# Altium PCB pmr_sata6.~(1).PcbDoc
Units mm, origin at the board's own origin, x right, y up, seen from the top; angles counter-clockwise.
Board outline 160 x 99.92 mm, 2 copper layers (Top Layer, Bottom Layer); 10 components, 40 nets, 165 pads, 0 vias.
Unrouted connection lines stored in the file: 105.
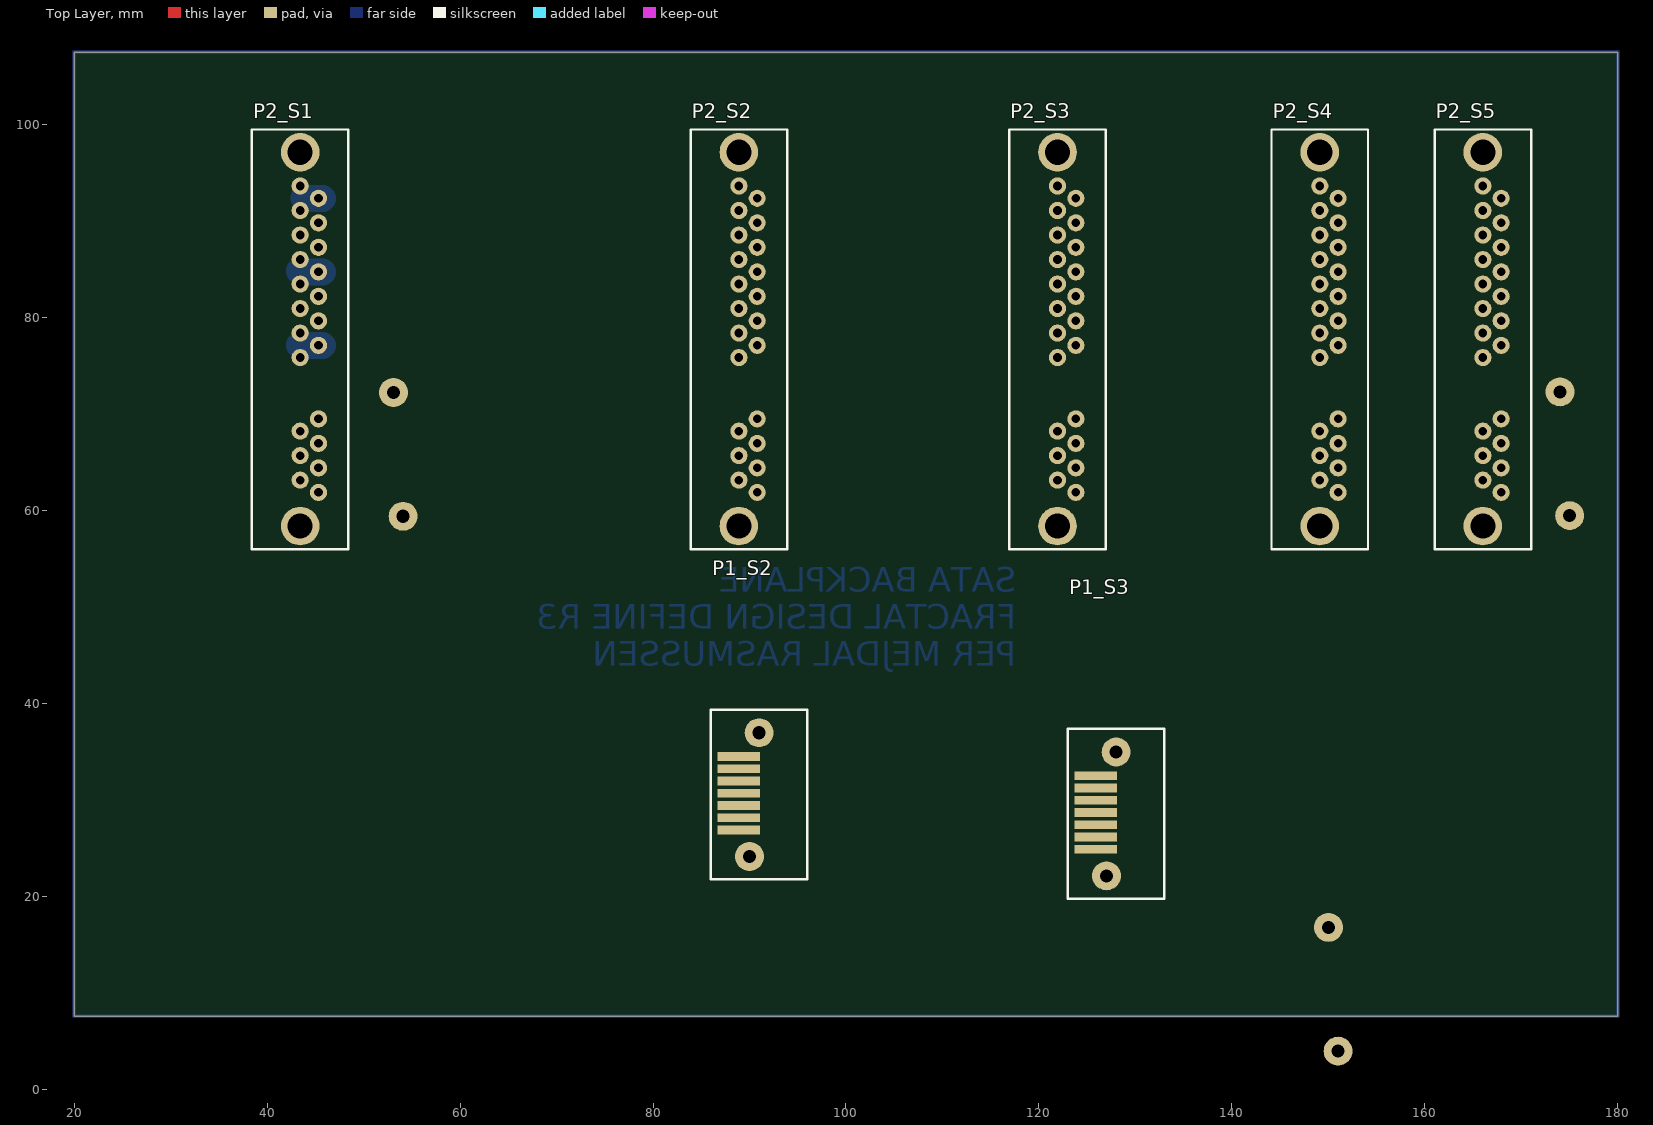
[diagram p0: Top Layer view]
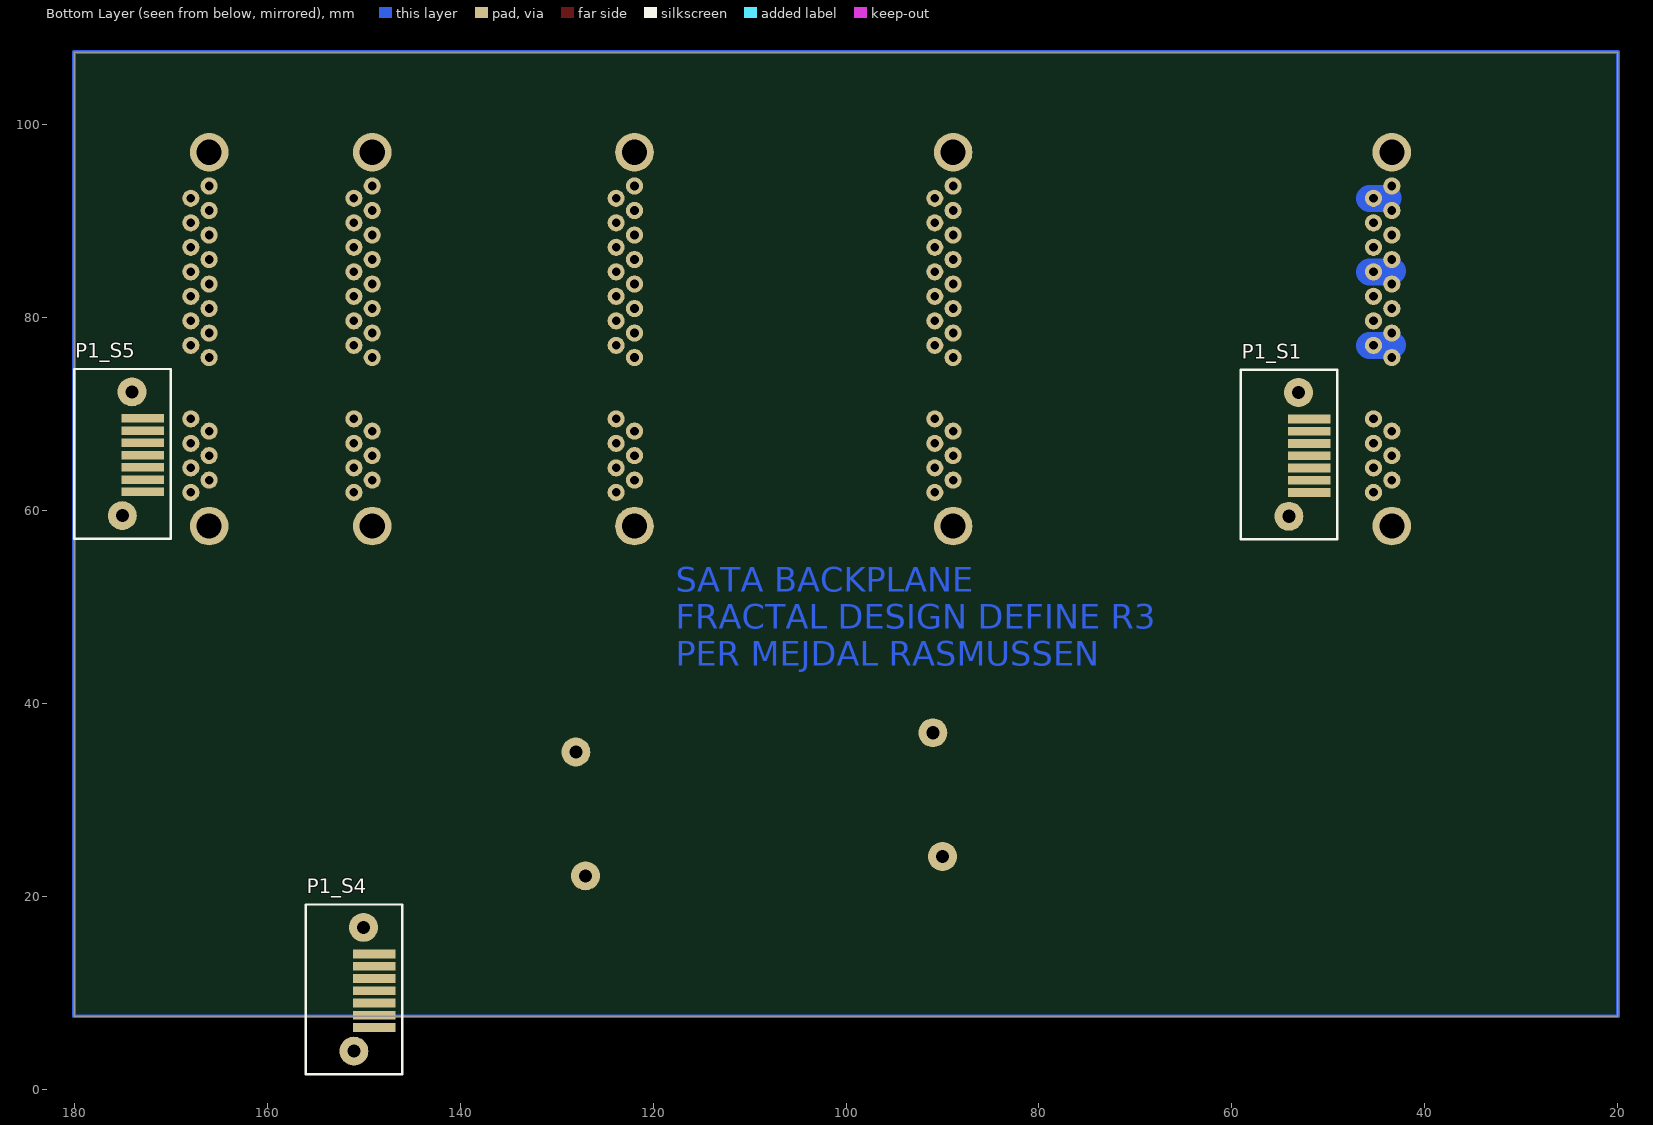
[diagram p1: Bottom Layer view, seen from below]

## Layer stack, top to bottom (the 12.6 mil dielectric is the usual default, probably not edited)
Top Solder: solder mask 0.0102, Solder Resist, Dk 3.5
Top Layer: signal copper 0.0356
Dielectric1: dielectric 0.32, FR-4, Dk 4.8
Bottom Layer: signal copper 0.0356
Bottom Solder: solder mask 0.0102, Solder Resist, Dk 3.5

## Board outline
20,7.62 20,107.544 180,107.544 180,7.62

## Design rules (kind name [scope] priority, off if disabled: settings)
Clearance [All] p1: gap=0.254
DiffPairsRouting [All] p1: maxlimit=0.254 minlimit=0.254 mostfreqgap=0.254 toplayer_minwidth=0.381 toplayer_maxwidth=0.381 toplayer_prefwidth=0.381 bottomlayer_minwidth=0.381 bottomlayer_maxwidth=0.381 bottomlayer_prefwidth=0.381 maxuncoupledlength=12.7
PolygonConnect [All] p1: connectstyle=Relief reliefconductorwidth=0.254 reliefentries=4 polygonreliefangle="90 Angle" airgapwidth=0.254
RoomDefinition S5 [InComponentClass('S5')] p1 off: confinementstyle=ConfineIn formatcopy=TRUE lockcomponents=FALSE outline 29,122 53,122 53,170 29,170
RoomDefinition S3 [InComponentClass('S3')] p2 off: confinementstyle=ConfineIn formatcopy=TRUE lockcomponents=FALSE outline 76,114.83 100,114.83 100,162.83 76,162.83
RoomDefinition S2 [InComponentClass('S2')] p3 off: confinementstyle=ConfineIn formatcopy=TRUE lockcomponents=FALSE outline 108,115 132,115 132,163 108,163
RoomDefinition S1 [InComponentClass('S1')] p4 off: confinementstyle=ConfineIn formatcopy=TRUE lockcomponents=FALSE outline 127,116 151,116 151,164 127,164
RoomDefinition S4 [InComponentClass('S4')] p5 off: confinementstyle=ConfineIn formatcopy=TRUE lockcomponents=FALSE outline 192.278,29.464 184.912,29.464 184.912,40.386 192.278,40.386
RoutingVias [All] p1: holewidth=0.711 width=1.27 viastyle="Through Hole" minholewidth=0.711 minwidth=1.27 maxholewidth=0.711 maxwidth=1.27
SilkToSolderMaskClearance SilkscreenOverComponentPads [IsPad] p1: minsilkscreentomaskgap=0.254 clearancetoexposedcopper=TRUE
SolderMaskExpansion [All] p1: expansion=0.102
Width [All] p1: maxlimit=12.7 minlimit=0.254 preferedwidth=0.254
28 further rules are at their usual default settings.

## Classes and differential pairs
channel class pmr_sata_single: S1 S2 S3 S4 S5
component class S5: P1_S5 P2_S5
component class S4: P1_S4 P2_S4
component class S3: P1_S3 P2_S3
component class S2: P1_S2 P2_S2
component class S1: P1_S1 P2_S1
differential pair PAIR2_S5: +PAIR2_S5_P -PAIR2_S5_N
differential pair PAIR2_S4: +PAIR2_S4_P -PAIR2_S4_N
differential pair PAIR2_S3: +PAIR2_S3_P -PAIR2_S3_N
differential pair PAIR2_S2: +PAIR2_S2_P -PAIR2_S2_N
differential pair PAIR2_S1: +PAIR2_S1_P -PAIR2_S1_N
differential pair PAIR1_S5: +PAIR1_S5_P -PAIR1_S5_N
differential pair PAIR1_S4: +PAIR1_S4_P -PAIR1_S4_N
differential pair PAIR1_S3: +PAIR1_S3_P -PAIR1_S3_N
differential pair PAIR1_S2: +PAIR1_S2_P -PAIR1_S2_N
differential pair PAIR1_S1: +PAIR1_S1_P -PAIR1_S1_N

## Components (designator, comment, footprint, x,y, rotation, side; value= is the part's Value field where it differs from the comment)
P1_S1 "SATA lille" "PMR_SATA -LILLE NY" 54.102,59.436 r270 bottom (schematic designator P1)
P1_S2 "SATA lille" "PMR_SATA -LILLE NY" 91,37 r90 top (schematic designator P1)
P1_S3 "SATA lille" "PMR_SATA -LILLE NY" 128,35 r90 top (schematic designator P1)
P1_S4 "SATA lille" "PMR_SATA -LILLE NY" 151,4 r270 bottom (schematic designator P1)
P1_S5 "SATA lille" "PMR_SATA -LILLE NY" 175,59.5 r270 bottom (schematic designator P1)
P2_S1 "SATA STOR" pmr_sata 43.434,58.42 r90 top (schematic designator P2)
P2_S2 "SATA STOR" pmr_sata 88.9,58.42 r90 top (schematic designator P2)
P2_S3 "SATA STOR" pmr_sata 121.92,58.42 r90 top (schematic designator P2)
P2_S4 "SATA STOR" pmr_sata 149.098,58.42 r90 top (schematic designator P2)
P2_S5 "SATA STOR" pmr_sata 166,58.42 r90 top (schematic designator P2)

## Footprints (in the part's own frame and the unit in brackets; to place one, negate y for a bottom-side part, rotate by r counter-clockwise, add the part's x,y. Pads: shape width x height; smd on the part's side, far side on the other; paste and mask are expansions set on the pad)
pmr_sata [mm]
  round 1.778 hole 0.9: P1(17.46,0) P2(18.73,-1.9) P3(20,0) P4(21.27,-1.9) P5(22.54,0) P6(23.81,-1.9) P7(25.08,0) P8(26.35,-1.9) P9(27.62,0) P10(28.89,-1.9) P11(30.16,0) P12(31.43,-1.9) P13(32.7,0) P14(33.97,-1.9) P15(35.24,0) S1(3.49,-1.9) S2(4.76,0) S3(6.03,-1.9) S4(7.3,0) S5(8.57,-1.9) S6(9.84,0) S7(11.11,-1.9)
  round 4 hole 2.6: S8(0,0) S8(38.74,0)
  silkscreen extent -2.4,-5 41.1,5
"PMR_SATA -LILLE NY" [mm]
  rect 0.9x4.4 smd: S1(-2.46,2.1) S2(-3.73,2.1) S3(-5,2.1) S4(-6.27,2.1) S5(-7.54,2.1) S6(-8.81,2.1) S7(-10.08,2.1)
  round 3 hole 1.35: S8(-12.83,1) S8(0,0)
  silkscreen extent -15.2,-5 2.4,5

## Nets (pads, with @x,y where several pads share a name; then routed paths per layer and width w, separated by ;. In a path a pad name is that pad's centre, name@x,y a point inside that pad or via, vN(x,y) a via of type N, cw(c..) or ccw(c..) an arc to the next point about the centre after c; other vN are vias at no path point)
GND1: P2_S1.P4 P2_S1.P5 P2_S1.P6 P2_S2.P4 P2_S2.P5 P2_S2.P6 P2_S3.P4 P2_S3.P5 P2_S3.P6 P2_S4.P4 P2_S4.P5 P2_S4.P6 P2_S5.P4 P2_S5.P5 P2_S5.P6
GND2: P2_S1.P10 P2_S1.P11 P2_S1.P12 P2_S2.P10 P2_S2.P11 P2_S2.P12 P2_S3.P10 P2_S3.P11 P2_S3.P12 P2_S4.P10 P2_S4.P11 P2_S4.P12 P2_S5.P10 P2_S5.P11 P2_S5.P12
NetP1_S1_S1: P1_S1.S1 P2_S1.S1
NetP1_S1_S4: P1_S1.S4 P2_S1.S4
NetP1_S1_S7: P1_S1.S7 P2_S1.S7
NetP1_S2_S1: P1_S2.S1 P2_S2.S1
NetP1_S2_S4: P1_S2.S4 P2_S2.S4
NetP1_S2_S7: P1_S2.S7 P2_S2.S7
NetP1_S3_S1: P1_S3.S1 P2_S3.S1
NetP1_S3_S4: P1_S3.S4 P2_S3.S4
NetP1_S3_S7: P1_S3.S7 P2_S3.S7
NetP1_S4_S1: P1_S4.S1 P2_S4.S1
NetP1_S4_S4: P1_S4.S4 P2_S4.S4
NetP1_S4_S7: P1_S4.S7 P2_S4.S7
NetP1_S5_S1: P1_S5.S1 P2_S5.S1
NetP1_S5_S4: P1_S5.S4 P2_S5.S4
NetP1_S5_S7: P1_S5.S7 P2_S5.S7
PAIR1_S1_N: P1_S1.S2 P2_S1.S2
PAIR1_S1_P: P1_S1.S3 P2_S1.S3
PAIR1_S2_N: P1_S2.S2 P2_S2.S2
PAIR1_S2_P: P1_S2.S3 P2_S2.S3
PAIR1_S3_N: P1_S3.S2 P2_S3.S2
PAIR1_S3_P: P1_S3.S3 P2_S3.S3
PAIR1_S4_N: P1_S4.S2 P2_S4.S2
PAIR1_S4_P: P1_S4.S3 P2_S4.S3
PAIR1_S5_N: P1_S5.S2 P2_S5.S2
PAIR1_S5_P: P1_S5.S3 P2_S5.S3
PAIR2_S1_N: P1_S1.S5 P2_S1.S5
PAIR2_S1_P: P1_S1.S6 P2_S1.S6
PAIR2_S2_N: P1_S2.S5 P2_S2.S5
PAIR2_S2_P: P1_S2.S6 P2_S2.S6
PAIR2_S3_N: P1_S3.S5 P2_S3.S5
PAIR2_S3_P: P1_S3.S6 P2_S3.S6
PAIR2_S4_N: P1_S4.S5 P2_S4.S5
PAIR2_S4_P: P1_S4.S6 P2_S4.S6
PAIR2_S5_N: P1_S5.S5 P2_S5.S5
PAIR2_S5_P: P1_S5.S6 P2_S5.S6
VCC1: P2_S1.P1 P2_S1.P2 P2_S1.P3 P2_S2.P1 P2_S2.P2 P2_S2.P3 P2_S3.P1 P2_S3.P2 P2_S3.P3 P2_S4.P1 P2_S4.P2 P2_S4.P3 P2_S5.P1 P2_S5.P2 P2_S5.P3
VCC2: P2_S1.P7 P2_S1.P8 P2_S1.P9 P2_S2.P7 P2_S2.P8 P2_S2.P9 P2_S3.P7 P2_S3.P8 P2_S3.P9 P2_S4.P7 P2_S4.P8 P2_S4.P9 P2_S5.P7 P2_S5.P8 P2_S5.P9
VCC3: P2_S1.P13 P2_S1.P14 P2_S1.P15 P2_S2.P13 P2_S2.P14 P2_S2.P15 P2_S3.P13 P2_S3.P14 P2_S3.P15 P2_S4.P13 P2_S4.P14 P2_S4.P15 P2_S5.P13 P2_S5.P14 P2_S5.P15
pads on no net: P1_S1.S8 P1_S2.S8 P1_S3.S8 P1_S4.S8 P1_S5.S8 P2_S1.S8 P2_S2.S8 P2_S3.S8 P2_S4.S8 P2_S5.S8
copper on no net: | length 527.6
  Bottom Layer w0.381: 45.11,67.005 45.151,66.965 45.74,66.965 ; 20,7.62 180,7.62 180,107.544 20,107.544 20,7.62
  Bottom Layer w0.508: 45.613,61.758 45.74,61.885 ; 45.613,69.632 45.74,69.505
  Bottom Layer w2.794: 43.383,77.165 43.424,77.125 45.74,77.125 ; 43.383,84.836 43.475,84.745 45.74,84.745 ; 43.815,92.431 43.881,92.365 45.74,92.365

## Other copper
Bottom Layer:
  text "SATA BACKPLANE" at 117.653,51.638 h2.54
  text "FRACTAL DESIGN DEFINE R3" at 117.653,47.803 h2.54
  text "PER MEJDAL RASMUSSEN" at 117.653,43.967 h2.54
